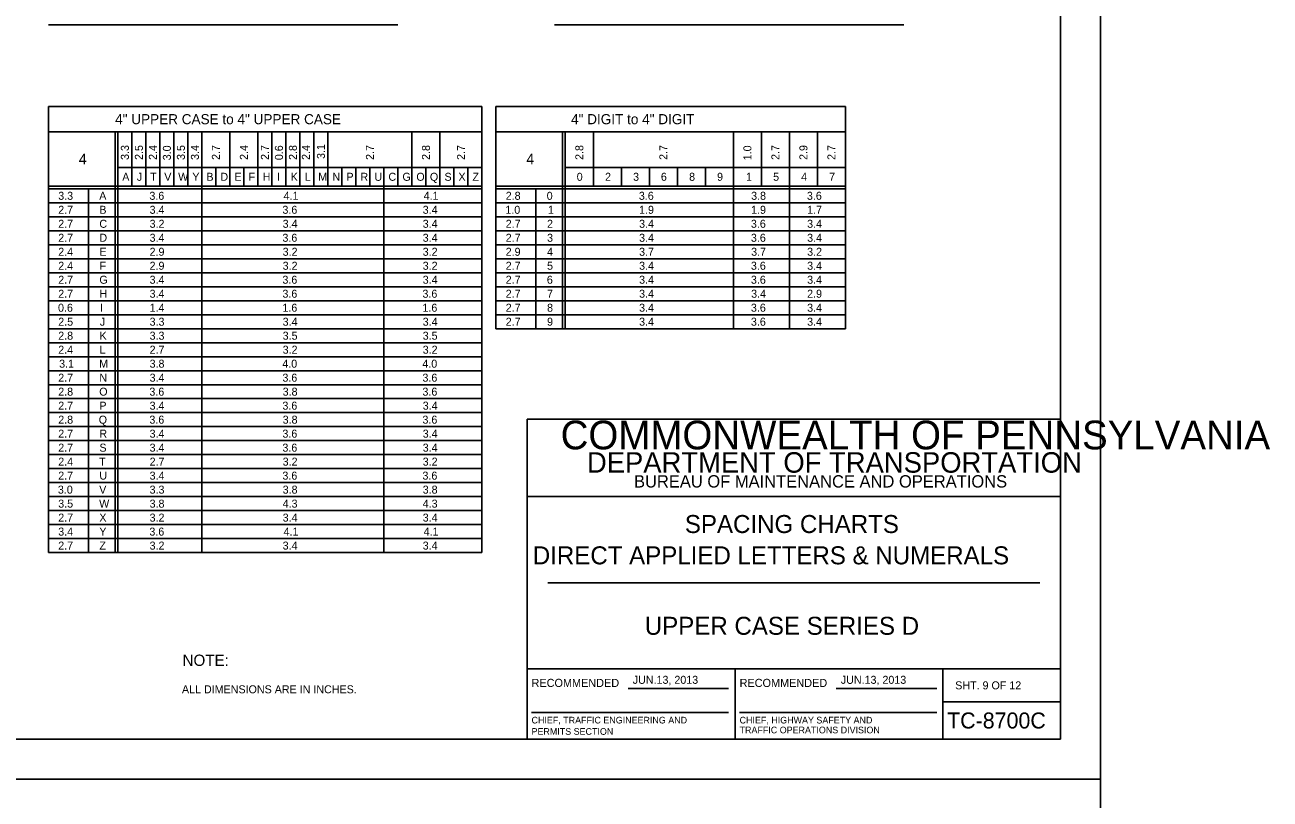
# Model space of a CAD drawing. Extents: x 638421 to 641849, y 297270 to 299646.
# Drawn here: x 640541.1 to 641007.9, y 297856.1 to 298146.6 of the extents above; entities that cross this region are included whole.
import ezdxf

# ---------------------------------------------------------------- set-up
doc = ezdxf.new("R2010")
doc.units = 0
for name, color, linetype in [('1', 7, 'Continuous'), ('2', 7, 'Continuous'), ('XCS-GRID-HVGL', 7, 'Continuous')]:
    doc.layers.add(name, color=color, linetype=linetype)

msp = doc.modelspace()

# ---------------------------------------------------------------- linework, layer by layer
at = {"layer": '1'}
for p, q in [((640929.31, 297878.63), (640929.31, 298442.63)), ((640729.31, 297878.63), (640729.31, 297998.63)), ((640729.31, 297998.63), (640929.31, 297998.63)), ((640929.31, 297969.63), (640729.31, 297969.63)), ((640737.06, 297937.31), (640921.56, 297937.31)), ((640729.31, 297905), (640929.31, 297905)), ((640807.31, 297905), (640807.31, 297878.63)), ((640885.19, 297878.63), (640885.19, 297905)), ((640767.24, 297897.57), (640804.87, 297897.57)), ((640845.24, 297897.57), (640882.87, 297897.57)), ((640885.19, 297892.63), (640929.31, 297892.63)), ((640730.99, 297888.68), (640804.87, 297888.68)), ((640808.99, 297888.68), (640882.87, 297888.68)), ((640929.31, 297878.63), (640143.31, 297878.63)), ((640143.31, 297878.63), (640729.31, 297878.63))]:
    msp.add_line(p, q, dxfattribs=at)
at = {"layer": '2'}
for p, q in [((640549.91, 298146.63), (640680.91, 298146.63)), ((640739.61, 298146.63), (640870.61, 298146.63)), ((640712.41, 298116), (640549.91, 298116)), ((640549.91, 298116), (640549.91, 297948.63)), ((640712.41, 298116), (640712.41, 297948.63)), ((640848.66, 298116), (640717.66, 298116)), ((640717.66, 298116), (640717.66, 298032.63)), ((640848.66, 298032.63), (640848.66, 298116)), ((640549.91, 298106.5), (640712.41, 298106.5)), ((640574.91, 298106.5), (640574.91, 297948.63)), ((640575.91, 298106.5), (640575.91, 297948.63)), ((640581.16, 298106.5), (640581.16, 298086.13)), ((640586.41, 298106.5), (640586.41, 298086.13)), ((640591.66, 298106.5), (640591.66, 298086.13)), ((640596.91, 298106.5), (640596.91, 298086.13)), ((640602.16, 298106.5), (640602.16, 298086.13)), ((640607.41, 298106.5), (640607.41, 297948.63)), ((640617.91, 298106.5), (640617.91, 298086.13)), ((640628.41, 298106.5), (640628.41, 298086.13)), ((640633.66, 298106.5), (640633.66, 298086.13)), ((640638.91, 298106.5), (640638.91, 298086.13)), ((640644.16, 298106.5), (640644.16, 298086.13)), ((640649.41, 298106.5), (640649.41, 298086.13)), ((640654.66, 298106.5), (640654.66, 298086.13)), ((640686.16, 298106.5), (640686.16, 298086.13)), ((640696.66, 298106.5), (640696.66, 298086.13)), ((640717.66, 298106.5), (640848.66, 298106.5)), ((640742.66, 298106.5), (640742.66, 298032.63)), ((640743.66, 298106.5), (640743.66, 298032.63)), ((640754.16, 298106.5), (640754.16, 298086.13)), ((640806.66, 298106.5), (640806.66, 298032.63)), ((640817.16, 298106.5), (640817.16, 298086.13)), ((640827.66, 298106.5), (640827.66, 298032.63)), ((640838.16, 298106.5), (640838.16, 298086.13)), ((640575.91, 298093.13), (640712.41, 298093.13)), ((640612.66, 298093.13), (640612.66, 298086.13)), ((640623.16, 298093.13), (640623.16, 298086.13)), ((640659.91, 298093.13), (640659.91, 298086.13)), ((640665.16, 298093.13), (640665.16, 298086.13)), ((640670.41, 298093.13), (640670.41, 298086.13)), ((640670.41, 298093.13), (640670.41, 298086.13)), ((640675.66, 298093.13), (640675.66, 297948.63)), ((640680.91, 298093.13), (640680.91, 298086.13)), ((640691.41, 298093.13), (640691.41, 298086.13)), ((640701.91, 298093.13), (640701.91, 298086.13)), ((640707.16, 298093.13), (640707.16, 298086.13)), ((640743.66, 298093.13), (640848.66, 298093.13)), ((640764.66, 298093.13), (640764.66, 298086.13)), ((640775.16, 298093.13), (640775.16, 298086.13)), ((640785.66, 298093.13), (640785.66, 298086.13)), ((640796.16, 298093.13), (640796.16, 298086.13)), ((640712.41, 298086.13), (640549.91, 298086.13)), ((640848.66, 298086.13), (640717.66, 298086.13)), ((640712.41, 298085.13), (640549.91, 298085.13)), ((640564.91, 298085.13), (640564.91, 297948.63)), ((640848.66, 298085.13), (640717.66, 298085.13)), ((640732.66, 298085.13), (640732.66, 298032.63)), ((640712.41, 298079.88), (640549.91, 298079.88)), ((640848.66, 298079.88), (640717.66, 298079.88)), ((640712.41, 298074.63), (640549.91, 298074.63)), ((640848.66, 298074.63), (640717.66, 298074.63)), ((640712.41, 298069.38), (640549.91, 298069.38)), ((640848.66, 298069.38), (640717.66, 298069.38)), ((640712.41, 298064.13), (640549.91, 298064.13)), ((640848.66, 298064.13), (640717.66, 298064.13)), ((640712.41, 298058.88), (640549.91, 298058.88)), ((640848.66, 298058.88), (640717.66, 298058.88)), ((640712.41, 298053.63), (640549.91, 298053.63)), ((640848.66, 298053.63), (640717.66, 298053.63)), ((640712.41, 298048.38), (640549.91, 298048.38)), ((640848.66, 298048.38), (640717.66, 298048.38)), ((640712.41, 298043.13), (640549.91, 298043.13)), ((640848.66, 298043.13), (640717.66, 298043.13)), ((640712.41, 298037.88), (640549.91, 298037.88)), ((640848.66, 298037.88), (640717.66, 298037.88)), ((640712.41, 298032.63), (640549.91, 298032.63)), ((640717.66, 298032.63), (640848.66, 298032.63)), ((640712.41, 298027.38), (640549.91, 298027.38)), ((640712.41, 298022.13), (640549.91, 298022.13)), ((640712.41, 298016.88), (640549.91, 298016.88)), ((640712.41, 298011.63), (640549.91, 298011.63)), ((640712.41, 298006.38), (640549.91, 298006.38)), ((640712.41, 298001.13), (640549.91, 298001.13)), ((640712.41, 297995.88), (640549.91, 297995.88)), ((640712.41, 297990.63), (640549.91, 297990.63)), ((640712.41, 297985.38), (640549.91, 297985.38)), ((640712.41, 297980.13), (640549.91, 297980.13)), ((640712.41, 297974.88), (640549.91, 297974.88)), ((640712.41, 297969.63), (640549.91, 297969.63)), ((640712.41, 297964.38), (640549.91, 297964.38)), ((640712.41, 297959.13), (640549.91, 297959.13)), ((640712.41, 297953.88), (640549.91, 297953.88)), ((640549.91, 297948.63), (640549.91, 297948.63)), ((640549.91, 297948.63), (640712.41, 297948.63))]:
    msp.add_line(p, q, dxfattribs=at)
at = {"layer": 'XCS-GRID-HVGL'}
for points in [[(640103.31, 298457.63), (640944.31, 298457.63), (640944.31, 297863.63), (640103.31, 297863.63)], [(640103.31, 297863.63), (640944.31, 297863.63), (640944.31, 297269.63), (640103.31, 297269.63)]]:
    msp.add_lwpolyline(points, close=True, dxfattribs=at)

# ---------------------------------------------------------------- texts
at = {"layer": '1'}
for s, height, p in [('COMMONWEALTH OF PENNSYLVANIA', 10.7828, (640741.9, 297987.36)), ('DEPARTMENT OF TRANSPORTATION', 7.6837, (640751.76, 297978.61)), ('BUREAU OF MAINTENANCE AND OPERATIONS', 4.6253, (640769.41, 297973.04)), ('SPACING CHARTS', 6.75, (640788.47, 297955.97)), ('DIRECT APPLIED LETTERS & NUMERALS', 6.75, (640731.47, 297944.22)), ('UPPER CASE SERIES D', 6.75, (640773.45, 297917.78)), ('RECOMMENDED', 3.048, (640730.99, 297898.2)), ('RECOMMENDED', 3.048, (640808.99, 297898.2)), ('SHT. 9 OF 12', 3, (640889.82, 297897.31)), ('CHIEF, TRAFFIC ENGINEERING AND', 2.5, (640730.99, 297884.51)), ('CHIEF, HIGHWAY SAFETY AND', 2.5, (640808.99, 297884.51)), ('TC-8700C', 6, (640886.77, 297882.63)), ('PERMITS SECTION', 2.5, (640730.99, 297880.26)), ('TRAFFIC OPERATIONS DIVISION', 2.5, (640808.99, 297880.81))]:
    msp.add_text(s, height=height, dxfattribs=at).set_placement(p)
at = {"layer": '2'}
for s, height, p in [('4" UPPER CASE to 4" UPPER CASE', 3.8, (640574.9, 298109.35)), ('4" DIGIT to 4" DIGIT', 3.8, (640745.81, 298109.35)), ('4', 4, (640561.28, 298094.31)), ('4', 4, (640729.03, 298094.31)), ('A', 3, (640577.56, 298088.13)), ('J', 3, (640583.04, 298088.13)), ('T', 3, (640588.04, 298088.13)), ('V', 3, (640593.31, 298088.13)), ('W', 3, (640598.53, 298088.13)), ('Y', 3, (640603.84, 298088.13)), ('B', 3, (640609.1, 298088.13)), ('D', 3, (640614.35, 298088.13)), ('E', 3, (640619.62, 298088.13)), ('F', 3, (640624.92, 298088.13)), ('H', 3, (640630.19, 298088.13)), ('I', 3, (640635.6, 298088.13)), ('K', 3, (640640.69, 298088.13)), ('L', 3, (640645.94, 298088.13)), ('M', 3, (640651.03, 298088.13)), ('N', 3, (640656.35, 298088.13)), ('P', 3, (640661.6, 298088.13)), ('R', 3, (640666.85, 298088.13)), ('U', 3, (640672.09, 298088.13)), ('C', 3, (640677.35, 298088.13)), ('G', 3, (640682.6, 298088.13)), ('O', 3, (640687.81, 298088.13)), ('Q', 3, (640692.88, 298088.13)), ('S', 3, (640698.37, 298088.13)), ('X', 3, (640703.59, 298088.13)), ('Z', 3, (640708.85, 298088.13)), ('0', 3, (640747.93, 298088.13)), ('2', 3, (640758.56, 298088.13)), ('3', 3, (640769.06, 298088.13)), ('6', 3, (640779.48, 298088.13)), ('8', 3, (640790.06, 298088.13)), ('9', 3, (640800.55, 298088.13)), ('1', 3, (640811.4, 298088.13)), ('5', 3, (640821.56, 298088.13)), ('4', 3, (640832.06, 298088.13)), ('7', 3, (640842.56, 298088.13)), ('3.3', 3, (640553.56, 298081)), ('A', 3, (640568.93, 298081)), ('3.6', 3, (640587.73, 298081)), ('4.1', 3, (640638.03, 298081)), ('4.1', 3, (640690.53, 298081)), ('2.8', 3, (640721.31, 298081)), ('0', 3, (640736.68, 298081)), ('3.6', 3, (640771.23, 298081)), ('3.8', 3, (640813.31, 298081)), ('3.6', 3, (640834.23, 298081)), ('2.7', 3, (640553.56, 298075.75)), ('B', 3, (640568.98, 298075.75)), ('3.4', 3, (640587.81, 298075.75)), ('3.6', 3, (640637.6, 298075.75)), ('3.4', 3, (640690.19, 298075.75)), ('1.0', 3, (640721.18, 298075.75)), ('1', 3, (640737.15, 298075.75)), ('1.9', 3, (640771.3, 298075.75)), ('1.9', 3, (640813.3, 298075.75)), ('1.7', 3, (640834.31, 298075.75)), ('2.7', 3, (640553.56, 298070.5)), ('C', 3, (640568.98, 298070.5)), ('3.2', 3, (640587.81, 298070.5)), ('3.4', 3, (640637.69, 298070.5)), ('3.4', 3, (640690.19, 298070.5)), ('2.7', 3, (640721.31, 298070.5)), ('2', 3, (640736.81, 298070.5)), ('3.4', 3, (640771.31, 298070.5)), ('3.6', 3, (640813.23, 298070.5)), ('3.4', 3, (640834.31, 298070.5)), ('2.7', 3, (640553.56, 298065.25)), ('D', 3, (640568.98, 298065.25)), ('3.4', 3, (640587.81, 298065.25)), ('3.6', 3, (640637.6, 298065.25)), ('3.4', 3, (640690.19, 298065.25)), ('2.7', 3, (640721.31, 298065.25)), ('3', 3, (640736.81, 298065.25)), ('3.4', 3, (640771.31, 298065.25)), ('3.6', 3, (640813.23, 298065.25)), ('3.4', 3, (640834.31, 298065.25)), ('2.4', 3, (640553.56, 298060)), ('E', 3, (640568.99, 298060)), ('2.9', 3, (640587.8, 298060)), ('3.2', 3, (640637.69, 298060)), ('3.2', 3, (640690.19, 298060)), ('2.9', 3, (640721.3, 298060)), ('4', 3, (640736.81, 298060)), ('3.7', 3, (640771.31, 298060)), ('3.7', 3, (640813.31, 298060)), ('3.2', 3, (640834.31, 298060)), ('2.4', 3, (640553.56, 298054.75)), ('2.9', 3, (640587.8, 298054.75)), ('3.2', 3, (640637.69, 298054.75)), ('3.2', 3, (640690.19, 298054.75)), ('2.7', 3, (640721.31, 298054.75)), ('3.4', 3, (640771.31, 298054.75)), ('3.6', 3, (640813.23, 298054.75)), ('3.4', 3, (640834.31, 298054.75)), ('F', 3, (640569.05, 298054.75)), ('5', 3, (640736.81, 298054.75)), ('2.7', 3, (640553.56, 298049.5)), ('G', 3, (640568.98, 298049.5)), ('3.4', 3, (640587.81, 298049.5)), ('3.6', 3, (640637.6, 298049.5)), ('3.4', 3, (640690.19, 298049.5)), ('2.7', 3, (640721.31, 298049.5)), ('6', 3, (640736.73, 298049.5)), ('3.4', 3, (640771.31, 298049.5)), ('3.6', 3, (640813.23, 298049.5)), ('3.4', 3, (640834.31, 298049.5)), ('2.7', 3, (640553.56, 298044.25)), ('H', 3, (640569.06, 298044.25)), ('3.4', 3, (640587.81, 298044.25)), ('3.6', 3, (640637.6, 298044.25)), ('3.6', 3, (640690.1, 298044.25)), ('2.7', 3, (640721.31, 298044.25)), ('7', 3, (640736.81, 298044.25)), ('3.4', 3, (640771.31, 298044.25)), ('3.4', 3, (640813.31, 298044.25)), ('2.9', 3, (640834.3, 298044.25)), ('0.6', 3, (640553.48, 298039)), ('I', 3, (640569.23, 298039)), ('1.4', 3, (640587.81, 298039)), ('1.6', 3, (640637.6, 298039)), ('1.6', 3, (640690.1, 298039)), ('2.7', 3, (640721.31, 298039)), ('8', 3, (640736.81, 298039)), ('3.4', 3, (640771.31, 298039)), ('3.6', 3, (640813.23, 298039)), ('3.4', 3, (640834.31, 298039)), ('2.5', 3, (640553.56, 298033.75)), ('J', 3, (640569.17, 298033.75)), ('3.3', 3, (640587.81, 298033.75)), ('3.4', 3, (640637.69, 298033.75)), ('3.4', 3, (640690.19, 298033.75)), ('2.7', 3, (640721.31, 298033.75)), ('9', 3, (640736.8, 298033.75)), ('3.4', 3, (640771.31, 298033.75)), ('3.6', 3, (640813.23, 298033.75)), ('3.4', 3, (640834.31, 298033.75)), ('2.8', 3, (640553.56, 298028.5)), ('K', 3, (640569.06, 298028.5)), ('3.3', 3, (640587.81, 298028.5)), ('3.5', 3, (640637.69, 298028.5)), ('3.5', 3, (640690.19, 298028.5)), ('2.4', 3, (640553.56, 298023.25)), ('L', 3, (640569.06, 298023.25)), ('2.7', 3, (640587.81, 298023.25)), ('3.2', 3, (640637.69, 298023.25)), ('3.2', 3, (640690.19, 298023.25)), ('3.1', 3, (640553.9, 298018)), ('M', 3, (640568.91, 298018)), ('3.8', 3, (640587.81, 298018)), ('4.0', 3, (640637.56, 298018)), ('4.0', 3, (640690.06, 298018)), ('2.7', 3, (640553.56, 298012.75)), ('3.4', 3, (640587.81, 298012.75)), ('3.6', 3, (640637.6, 298012.75)), ('3.6', 3, (640690.1, 298012.75)), ('N', 3, (640568.98, 298012.75)), ('2.8', 3, (640553.56, 298007.5)), ('O', 3, (640568.93, 298007.5)), ('3.6', 3, (640587.73, 298007.5)), ('3.8', 3, (640637.69, 298007.5)), ('3.6', 3, (640690.1, 298007.5)), ('2.7', 3, (640553.56, 298002.25)), ('P', 3, (640568.98, 298002.25)), ('3.4', 3, (640587.81, 298002.25)), ('3.6', 3, (640637.6, 298002.25)), ('3.4', 3, (640690.19, 298002.25)), ('2.8', 3, (640553.56, 297997)), ('Q', 3, (640568.75, 297997)), ('3.6', 3, (640587.73, 297997)), ('3.8', 3, (640637.69, 297997)), ('3.6', 3, (640690.1, 297997)), ('2.7', 3, (640553.56, 297991.75)), ('R', 3, (640568.98, 297991.75)), ('3.4', 3, (640587.81, 297991.75)), ('3.6', 3, (640637.6, 297991.75)), ('3.4', 3, (640690.19, 297991.75)), ('2.7', 3, (640553.56, 297986.5)), ('S', 3, (640568.99, 297986.5)), ('3.4', 3, (640587.81, 297986.5)), ('3.6', 3, (640637.6, 297986.5)), ('3.4', 3, (640690.19, 297986.5)), ('2.4', 3, (640553.56, 297981.25)), ('T', 3, (640568.92, 297981.25)), ('2.7', 3, (640587.81, 297981.25)), ('3.2', 3, (640637.69, 297981.25)), ('3.2', 3, (640690.19, 297981.25)), ('2.7', 3, (640553.56, 297976)), ('U', 3, (640568.97, 297976)), ('3.4', 3, (640587.81, 297976)), ('3.6', 3, (640637.6, 297976)), ('3.6', 3, (640690.1, 297976)), ('3.0', 3, (640553.43, 297970.75)), ('3.3', 3, (640587.81, 297970.75)), ('3.8', 3, (640637.69, 297970.75)), ('3.8', 3, (640690.19, 297970.75)), ('V', 3, (640568.93, 297970.75)), ('3.5', 3, (640553.56, 297965.5)), ('W', 3, (640568.91, 297965.5)), ('3.8', 3, (640587.81, 297965.5)), ('4.3', 3, (640637.69, 297965.5)), ('4.3', 3, (640690.19, 297965.5)), ('2.7', 3, (640553.56, 297960.25)), ('X', 3, (640568.97, 297960.25)), ('3.2', 3, (640587.81, 297960.25)), ('3.4', 3, (640637.69, 297960.25)), ('3.4', 3, (640690.19, 297960.25)), ('3.4', 3, (640553.56, 297955)), ('Y', 3, (640568.97, 297955)), ('3.6', 3, (640587.73, 297955)), ('4.1', 3, (640638.03, 297955)), ('4.1', 3, (640690.53, 297955)), ('2.7', 3, (640553.56, 297949.75)), ('Z', 3, (640568.98, 297949.75)), ('3.2', 3, (640587.81, 297949.75)), ('3.4', 3, (640637.69, 297949.75)), ('3.4', 3, (640690.19, 297949.75)), ('NOTE:', 4.25, (640600.16, 297906.1)), ('JUN.13, 2013', 3, (640768.93, 297899.39)), ('JUN.13, 2013', 3, (640846.93, 297899.39)), ('ALL DIMENSIONS ARE IN INCHES.', 3, (640599.94, 297895.83))]:
    msp.add_text(s, height=height, dxfattribs=at).set_placement(p)
for s, p in [('3.3', (640580.04, 298095.96)), ('2.5', (640585.29, 298095.96)), ('2.4', (640590.54, 298095.96)), ('3.0', (640595.79, 298095.83)), ('3.5', (640601.04, 298095.96)), ('3.4', (640606.29, 298095.96)), ('2.7', (640614.16, 298095.96)), ('2.4', (640624.66, 298095.96)), ('2.7', (640632.54, 298095.96)), ('0.6', (640637.79, 298095.88)), ('2.8', (640643.04, 298095.96)), ('2.4', (640647.9, 298095.96)), ('3.1', (640653.54, 298096.31)), ('2.7', (640671.91, 298095.96)), ('2.8', (640692.91, 298095.96)), ('2.7', (640706.04, 298095.96)), ('2.8', (640750.41, 298095.96)), ('2.7', (640781.91, 298095.96)), ('1.0', (640813.41, 298095.83)), ('2.7', (640823.91, 298095.96)), ('2.9', (640834.41, 298095.95)), ('2.7', (640844.91, 298095.96))]:
    msp.add_text(s, height=3, rotation=90, dxfattribs=at).set_placement(p)

doc.saveas('drawing.dxf')
